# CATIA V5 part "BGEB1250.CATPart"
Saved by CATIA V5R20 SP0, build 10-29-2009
Part number: BGEB1250
Revision: 10
Definition: design
Nomenclature: BGEB1250
Source: made
Description: NOT SPECIFIED
Bounding box of the stored display mesh (mm): x -27.648 to 27.648, y -27.648 to 27.648, z -16.002 to 28.448
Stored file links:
  C:\Users\Utente\Desktop\3D files BGEB\BGEB1250.CATPart
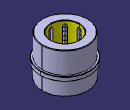
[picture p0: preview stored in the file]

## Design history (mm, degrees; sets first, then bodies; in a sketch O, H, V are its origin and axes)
Body1 "MANIFOLD_SOLID_BREP #38" (main body)
  Solid1: solid without history
Body2 "MANIFOLD_SOLID_BREP #76"
  Solid2: solid without history
Body3 "MANIFOLD_SOLID_BREP #114"
  Solid3: solid without history
Body4 "MANIFOLD_SOLID_BREP #152"
  Solid4: solid without history
Body5 "MANIFOLD_SOLID_BREP #190"
  Solid5: solid without history
Body6 "MANIFOLD_SOLID_BREP #228"
  Solid6: solid without history
Body7 "MANIFOLD_SOLID_BREP #266"
  Solid7: solid without history
Body8 "MANIFOLD_SOLID_BREP #304"
  Solid8: solid without history
Body9 "MANIFOLD_SOLID_BREP #2380"
  Solid9: solid without history
Body10 "MANIFOLD_SOLID_BREP #2418"
  Solid10: solid without history
Body11 "MANIFOLD_SOLID_BREP #2456"
  Solid11: solid without history
Body12 "MANIFOLD_SOLID_BREP #2494"
  Solid12: solid without history
Body13 "MANIFOLD_SOLID_BREP #2532"
  Solid13: solid without history
Body14 "MANIFOLD_SOLID_BREP #2570"
  Solid14: solid without history
Body15 "MANIFOLD_SOLID_BREP #2608"
  Solid15: solid without history
Body16 "MANIFOLD_SOLID_BREP #2646"
  Solid16: solid without history
Body17 "MANIFOLD_SOLID_BREP #2684"
  Solid17: solid without history
Body18 "MANIFOLD_SOLID_BREP #2722"
  Solid18: solid without history
Body19 "MANIFOLD_SOLID_BREP #2760"
  Solid19: solid without history
Body20 "MANIFOLD_SOLID_BREP #2798"
  Solid20: solid without history
Body21 "MANIFOLD_SOLID_BREP #2836"
  Solid21: solid without history
Body22 "MANIFOLD_SOLID_BREP #2874"
  Solid22: solid without history
Body23 "MANIFOLD_SOLID_BREP #2912"
  Solid23: solid without history
Body24 "MANIFOLD_SOLID_BREP #2950"
  Solid24: solid without history
Body25 "MANIFOLD_SOLID_BREP #2988"
  Solid25: solid without history
Body26 "MANIFOLD_SOLID_BREP #3026"
  Solid26: solid without history
Body27 "MANIFOLD_SOLID_BREP #3064"
  Solid27: solid without history
Body28 "MANIFOLD_SOLID_BREP #3102"
  Solid28: solid without history
Body29 "MANIFOLD_SOLID_BREP #3140"
  Solid29: solid without history
Body30 "MANIFOLD_SOLID_BREP #3178"
  Solid30: solid without history
Body31 "MANIFOLD_SOLID_BREP #3216"
  Solid31: solid without history
Body32 "MANIFOLD_SOLID_BREP #3254"
  Solid32: solid without history
Body33 "MANIFOLD_SOLID_BREP #3292"
  Solid33: solid without history
Body34 "MANIFOLD_SOLID_BREP #3330"
  Solid34: solid without history
Body35 "MANIFOLD_SOLID_BREP #3368"
  Solid35: solid without history
Body36 "MANIFOLD_SOLID_BREP #3406"
  Solid36: solid without history
Body37 "MANIFOLD_SOLID_BREP #3444"
  Solid37: solid without history
Body38 "MANIFOLD_SOLID_BREP #3482"
  Solid38: solid without history
Body39 "MANIFOLD_SOLID_BREP #3520"
  Solid39: solid without history
Body40 "MANIFOLD_SOLID_BREP #3558"
  Solid40: solid without history
Body41 "MANIFOLD_SOLID_BREP #3596"
  Solid41: solid without history
Body42 "MANIFOLD_SOLID_BREP #3634"
  Solid42: solid without history
Body43 "MANIFOLD_SOLID_BREP #3672"
  Solid43: solid without history
Body44 "MANIFOLD_SOLID_BREP #3710"
  Solid44: solid without history
Body45 "MANIFOLD_SOLID_BREP #3748"
  Solid45: solid without history
Body46 "MANIFOLD_SOLID_BREP #3786"
  Solid46: solid without history
Body47 "MANIFOLD_SOLID_BREP #3824"
  Solid47: solid without history
Body48 "MANIFOLD_SOLID_BREP #3862"
  Solid48: solid without history
Body49 "MANIFOLD_SOLID_BREP #3900"
  Solid49: solid without history
Body50 "MANIFOLD_SOLID_BREP #3938"
  Solid50: solid without history
Body51 "MANIFOLD_SOLID_BREP #3976"
  Solid51: solid without history
Body52 "MANIFOLD_SOLID_BREP #4014"
  Solid52: solid without history
Body53 "MANIFOLD_SOLID_BREP #4052"
  Solid53: solid without history
Body54 "MANIFOLD_SOLID_BREP #4090"
  Solid54: solid without history
Body55 "MANIFOLD_SOLID_BREP #4128"
  Solid55: solid without history
Body56 "MANIFOLD_SOLID_BREP #4166"
  Solid56: solid without history
Body57 "MANIFOLD_SOLID_BREP #4204"
  Solid57: solid without history
Body58 "MANIFOLD_SOLID_BREP #4242"
  Solid58: solid without history
Body59 "MANIFOLD_SOLID_BREP #4280"
  Solid59: solid without history
Body60 "MANIFOLD_SOLID_BREP #4318"
  Solid60: solid without history
Body61 "MANIFOLD_SOLID_BREP #4356"
  Solid61: solid without history
Body62 "MANIFOLD_SOLID_BREP #4394"
  Solid62: solid without history
Body63 "MANIFOLD_SOLID_BREP #4432"
  Solid63: solid without history
Body64 "MANIFOLD_SOLID_BREP #4470"
  Solid64: solid without history
Body65 "MANIFOLD_SOLID_BREP #4508"
  Solid65: solid without history
Body66 "MANIFOLD_SOLID_BREP #4546"
  Solid66: solid without history
Body67 "MANIFOLD_SOLID_BREP #4584"
  Solid67: solid without history
Body68 "MANIFOLD_SOLID_BREP #4622"
  Solid68: solid without history
Body69 "MANIFOLD_SOLID_BREP #4660"
  Solid69: solid without history
Body70 "MANIFOLD_SOLID_BREP #4698"
  Solid70: solid without history
Body71 "MANIFOLD_SOLID_BREP #4736"
  Solid71: solid without history
Body72 "MANIFOLD_SOLID_BREP #4774"
  Solid72: solid without history
Body73 "MANIFOLD_SOLID_BREP #4812"
  Solid73: solid without history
